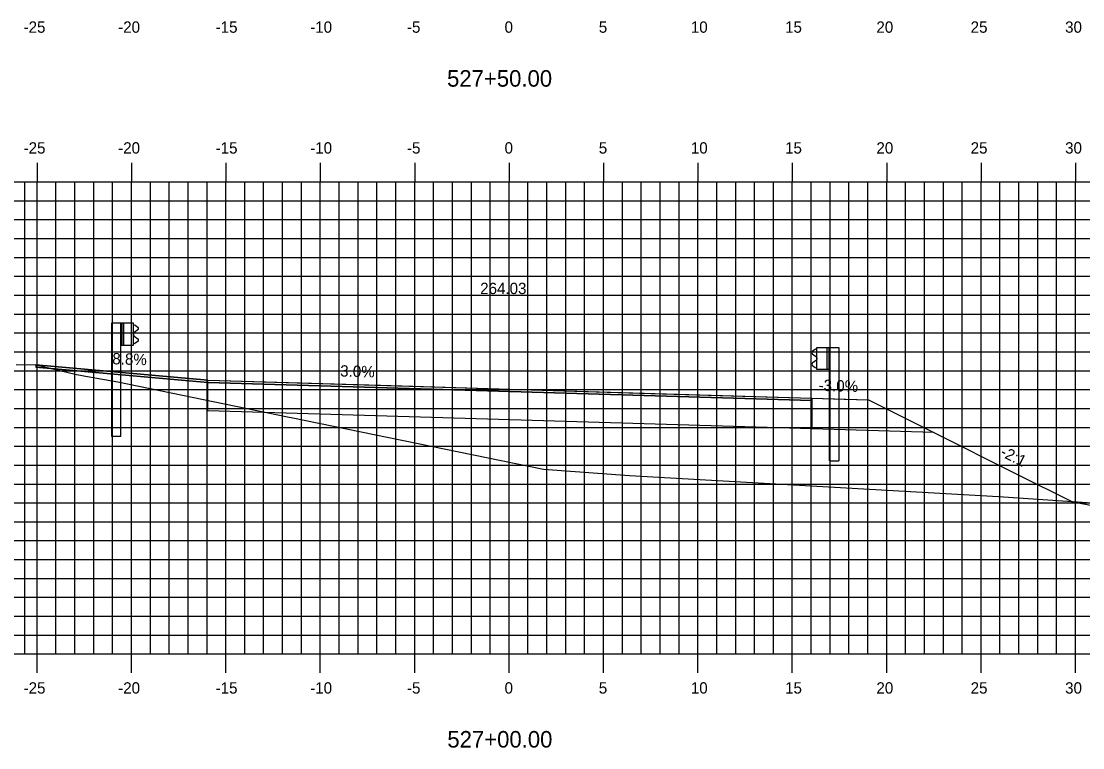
# Model space of a CAD drawing. Extents: x 1170543 to 1177585, y 609599 to 610623.
# Drawn here: x 1176144.5 to 1176200.8, y 610272.8 to 610311.3 of the extents above; entities that cross this region are included whole.
import ezdxf

# ---------------------------------------------------------------- set-up
doc = ezdxf.new("R2010")
doc.units = 0
for name, color, linetype in [('_Construction', 7, 'Continuous'), ('ANNOTATION', 7, 'Continuous'), ('D_Guardrail_Beam_Lt', 7, 'Continuous'), ('D_Guardrail_Beam_Rt', 7, 'Continuous'), ('D_Roadway_Centerline', 7, 'Continuous'), ('D_Roadway_Centerline_Text', 7, 'Continuous'), ('D_Roadway_Edge_Pavement', 7, 'Continuous'), ('D_Roadway_Edge_Shoulder', 7, 'Continuous'), ('D_Roadway_Edge_TW', 7, 'Continuous'), ('D_Roadway_Pavement', 7, 'Continuous'), ('D_Roadway_SubGrade', 7, 'Continuous'), ('H_V ANNOTATION', 7, 'Continuous'), ('MAJOR', 7, 'Continuous'), ('MINOR', 7, 'Continuous'), ('S_Roadway_Centerline', 7, 'Continuous')]:
    doc.layers.add(name, color=color, linetype=linetype)

msp = doc.modelspace()

# ---------------------------------------------------------------- linework, layer by layer
at = {"layer": '_Construction'}
for p, q in [((1176144.745, 610277.801), (1176144.745, 610302.801)), ((1176154.41, 610292.182), (1176145.315, 610292.982)), ((1176154.421, 610292.307), (1176145.326, 610293.106))]:
    msp.add_line(p, q, dxfattribs=at)
at = {"layer": 'D_Guardrail_Beam_Lt'}
for p, q in [((1176149.331, 610295.314), (1176149.331, 610289.314)), ((1176149.802, 610295.314), (1176149.331, 610295.314)), ((1176150.49, 610295.314), (1176149.802, 610295.314)), ((1176149.802, 610295.314), (1176149.802, 610294.147)), ((1176149.865, 610295.314), (1176149.865, 610294.147)), ((1176149.969, 610295.314), (1176149.969, 610294.147)), ((1176150.49, 610294.147), (1176150.49, 610295.314)), ((1176150.49, 610295.23), (1176150.564, 610295.216)), ((1176150.723, 610294.966), (1176150.528, 610294.83)), ((1176150.58, 610295.209), (1176150.723, 610295.109)), ((1176150.494, 610294.766), (1176150.494, 610294.695)), ((1176150.528, 610294.631), (1176150.723, 610294.495)), ((1176150.723, 610294.352), (1176150.58, 610294.252)), ((1176149.802, 610294.147), (1176150.49, 610294.147)), ((1176149.823, 610289.314), (1176149.823, 610294.147)), ((1176150.564, 610294.245), (1176150.49, 610294.23)), ((1176149.823, 610289.314), (1176149.331, 610289.314))]:
    msp.add_line(p, q, dxfattribs=at)
for centre, major_axis, start_param, end_param in [((1176150.556, 610295.175), (0.0417, 0), 0.959931, 1.376053), ((1176150.673, 610295.038), (0.0877, 0), 5.323254, 7.243116), ((1176150.573, 610294.766), (-0.0789, 0), 5.323254, 6.283185), ((1176150.573, 610294.695), (-0.0789, 0), 6.283185, 7.243116), ((1176150.673, 610294.423), (0.0877, 0), 5.323254, 7.243116), ((1176150.556, 610294.286), (0.0417, 0), 4.907132, 5.323254)]:
    msp.add_ellipse(centre, major_axis=major_axis, ratio=0.995501, start_param=start_param, end_param=end_param, dxfattribs=at)
at = {"layer": 'D_Guardrail_Beam_Rt'}
for p, q in [((1176186.601, 610293.928), (1176186.458, 610293.828)), ((1176186.691, 610293.949), (1176186.617, 610293.934)), ((1176186.691, 610294.032), (1176187.379, 610294.032)), ((1176186.691, 610292.866), (1176186.691, 610294.032)), ((1176187.212, 610294.032), (1176187.212, 610292.866)), ((1176187.316, 610294.032), (1176187.316, 610292.866)), ((1176187.379, 610294.032), (1176187.85, 610294.032)), ((1176187.379, 610294.032), (1176187.379, 610292.866)), ((1176187.85, 610294.032), (1176187.85, 610288.032)), ((1176186.458, 610293.685), (1176186.653, 610293.548)), ((1176186.653, 610293.349), (1176186.458, 610293.213)), ((1176186.687, 610293.484), (1176186.687, 610293.414)), ((1176186.458, 610293.07), (1176186.601, 610292.97)), ((1176186.617, 610292.963), (1176186.691, 610292.949)), ((1176187.379, 610292.866), (1176186.691, 610292.866)), ((1176187.358, 610288.032), (1176187.358, 610292.866)), ((1176187.358, 610288.032), (1176187.85, 610288.032))]:
    msp.add_line(p, q, dxfattribs=at)
for centre, major_axis, start_param, end_param in [((1176186.508, 610293.756), (-0.0877, 0), 5.323254, 7.243116), ((1176186.625, 610293.894), (-0.0417, 0), 4.907132, 5.323254), ((1176186.508, 610293.142), (-0.0877, 0), 5.323254, 7.243116), ((1176186.608, 610293.484), (0.0789, 0), 0, 0.959931), ((1176186.608, 610293.414), (0.0789, 0), 5.323254, 6.283185), ((1176186.625, 610293.004), (-0.0417, 0), 0.959931, 1.376053)]:
    msp.add_ellipse(centre, major_axis=major_axis, ratio=0.995501, start_param=start_param, end_param=end_param, dxfattribs=at)
at = {"layer": 'D_Roadway_Centerline'}
msp.add_lwpolyline([(1176145.326, 610293.106), (1176145.326, 610293.106), (1176145.326, 610293.106), (1176154.421, 610292.307), (1176154.421, 610292.307), (1176154.421, 610292.307), (1176163.579, 610292.033), (1176170.421, 610291.827), (1176177.292, 610291.619), (1176186.42, 610291.347), (1176188.135, 610291.295), (1176189.42, 610291.257), (1176190.903, 610290.515), (1176192.878, 610289.528), (1176197.239, 610287.348), (1176200.181, 610285.876)], dxfattribs=at)
at = {"layer": 'D_Roadway_Edge_Pavement'}
msp.add_lwpolyline([(1176200.17, 610285.882), (1176205.78, 610284.801), (1176207.048, 610284.379), (1176208.783, 610283.801), (1176210.06, 610283.376), (1176211.786, 610282.801), (1176218.086, 610282.801), (1176240.385, 610282.801)], dxfattribs=at)
at = {"layer": 'D_Roadway_Edge_Shoulder'}
for points in [[(1176154.421, 610292.307), (1176145.326, 610293.106), (1176145.326, 610292.981), (1176154.421, 610292.182)], [(1176186.42, 610291.347), (1176186.42, 610291.222)]]:
    msp.add_lwpolyline(points, dxfattribs=at)
at = {"layer": 'D_Roadway_Edge_TW'}
msp.add_lwpolyline([(1176154.421, 610292.182), (1176154.421, 610292.307), (1176170.421, 610291.827), (1176186.42, 610291.347), (1176186.42, 610291.222), (1176170.421, 610291.702)], close=True, dxfattribs=at)
at = {"layer": 'D_Roadway_Pavement'}
msp.add_lwpolyline([(1176154.421, 610292.182), (1176154.421, 610292.182), (1176170.421, 610291.702), (1176186.42, 610291.222), (1176186.42, 610291.222), (1176170.421, 610291.702)], close=True, dxfattribs=at)
for points in [[(1176154.421, 610292.182), (1176154.421, 610292.182)], [(1176154.421, 610292.182), (1176154.421, 610292.182)], [(1176186.42, 610291.222), (1176186.42, 610291.222)], [(1176186.42, 610291.222), (1176186.42, 610291.222)]]:
    msp.add_lwpolyline(points, dxfattribs=at)
at = {"layer": 'D_Roadway_SubGrade'}
for points in [[(1176154.421, 610290.682), (1176154.421, 610292.182), (1176170.421, 610291.702), (1176186.42, 610291.222), (1176186.42, 610289.722), (1176170.421, 610290.202)], [(1176186.42, 610291.347), (1176189.42, 610291.257), (1176192.878, 610289.528), (1176186.42, 610289.722)]]:
    msp.add_lwpolyline(points, close=True, dxfattribs=at)
at = {"layer": 'MAJOR'}
for p, q in [((1176145.385, 610303.803), (1176145.385, 610302.801)), ((1176150.385, 610303.803), (1176150.385, 610302.801)), ((1176155.385, 610303.803), (1176155.385, 610302.801)), ((1176160.385, 610303.803), (1176160.385, 610302.801)), ((1176165.385, 610303.803), (1176165.385, 610302.801)), ((1176170.385, 610303.803), (1176170.385, 610302.801)), ((1176175.385, 610303.803), (1176175.385, 610302.801)), ((1176180.385, 610303.803), (1176180.385, 610302.801)), ((1176185.385, 610303.803), (1176185.385, 610302.801)), ((1176190.385, 610303.803), (1176190.385, 610302.801)), ((1176195.385, 610303.803), (1176195.385, 610302.801)), ((1176200.385, 610303.803), (1176200.385, 610302.801)), ((1176100.385, 610302.801), (1176240.385, 610302.801)), ((1176100.385, 610302.801), (1176240.385, 610302.801)), ((1176145.385, 610277.801), (1176145.385, 610302.801)), ((1176150.385, 610277.801), (1176150.385, 610302.801)), ((1176155.385, 610277.801), (1176155.385, 610302.801)), ((1176160.385, 610277.801), (1176160.385, 610302.801)), ((1176165.385, 610277.801), (1176165.385, 610302.801)), ((1176170.385, 610277.801), (1176170.385, 610302.801)), ((1176175.385, 610277.801), (1176175.385, 610302.801)), ((1176180.385, 610277.801), (1176180.385, 610302.801)), ((1176185.385, 610277.801), (1176185.385, 610302.801)), ((1176190.385, 610277.801), (1176190.385, 610302.801)), ((1176195.385, 610277.801), (1176195.385, 610302.801)), ((1176200.385, 610277.801), (1176200.385, 610302.801)), ((1176100.385, 610297.801), (1176240.385, 610297.801)), ((1176100.385, 610292.801), (1176240.385, 610292.801)), ((1176100.385, 610287.801), (1176240.385, 610287.801)), ((1176100.385, 610282.801), (1176240.385, 610282.801)), ((1176100.385, 610277.801), (1176240.385, 610277.801)), ((1176100.385, 610277.801), (1176240.385, 610277.801)), ((1176145.385, 610276.799), (1176145.385, 610277.801)), ((1176150.385, 610276.799), (1176150.385, 610277.801)), ((1176155.385, 610276.799), (1176155.385, 610277.801)), ((1176160.385, 610276.799), (1176160.385, 610277.801)), ((1176165.385, 610276.799), (1176165.385, 610277.801)), ((1176170.385, 610276.799), (1176170.385, 610277.801)), ((1176175.385, 610276.799), (1176175.385, 610277.801)), ((1176180.385, 610276.799), (1176180.385, 610277.801)), ((1176185.385, 610276.799), (1176185.385, 610277.801)), ((1176190.385, 610276.799), (1176190.385, 610277.801)), ((1176195.385, 610276.799), (1176195.385, 610277.801)), ((1176200.385, 610276.799), (1176200.385, 610277.801))]:
    msp.add_line(p, q, dxfattribs=at)
at = {"layer": 'MINOR'}
for p, q in [((1176146.385, 610277.801), (1176146.385, 610302.801)), ((1176147.385, 610277.801), (1176147.385, 610302.801)), ((1176148.385, 610277.801), (1176148.385, 610302.801)), ((1176149.385, 610277.801), (1176149.385, 610302.801)), ((1176151.385, 610277.801), (1176151.385, 610302.801)), ((1176152.385, 610277.801), (1176152.385, 610302.801)), ((1176153.385, 610277.801), (1176153.385, 610302.801)), ((1176154.385, 610277.801), (1176154.385, 610302.801)), ((1176156.385, 610277.801), (1176156.385, 610302.801)), ((1176157.385, 610277.801), (1176157.385, 610302.801)), ((1176158.385, 610277.801), (1176158.385, 610302.801)), ((1176159.385, 610277.801), (1176159.385, 610302.801)), ((1176161.385, 610277.801), (1176161.385, 610302.801)), ((1176162.385, 610277.801), (1176162.385, 610302.801)), ((1176163.385, 610277.801), (1176163.385, 610302.801)), ((1176164.385, 610277.801), (1176164.385, 610302.801)), ((1176166.385, 610277.801), (1176166.385, 610302.801)), ((1176167.385, 610277.801), (1176167.385, 610302.801)), ((1176168.385, 610277.801), (1176168.385, 610302.801)), ((1176169.385, 610277.801), (1176169.385, 610302.801)), ((1176171.385, 610277.801), (1176171.385, 610302.801)), ((1176172.385, 610277.801), (1176172.385, 610302.801)), ((1176173.385, 610277.801), (1176173.385, 610302.801)), ((1176174.385, 610277.801), (1176174.385, 610302.801)), ((1176176.385, 610277.801), (1176176.385, 610302.801)), ((1176177.385, 610277.801), (1176177.385, 610302.801)), ((1176178.385, 610277.801), (1176178.385, 610302.801)), ((1176179.385, 610277.801), (1176179.385, 610302.801)), ((1176181.385, 610277.801), (1176181.385, 610302.801)), ((1176182.385, 610277.801), (1176182.385, 610302.801)), ((1176183.385, 610277.801), (1176183.385, 610302.801)), ((1176184.385, 610277.801), (1176184.385, 610302.801)), ((1176186.385, 610277.801), (1176186.385, 610302.801)), ((1176187.385, 610277.801), (1176187.385, 610302.801)), ((1176188.385, 610277.801), (1176188.385, 610302.801)), ((1176189.385, 610277.801), (1176189.385, 610302.801)), ((1176191.385, 610277.801), (1176191.385, 610302.801)), ((1176192.385, 610277.801), (1176192.385, 610302.801)), ((1176193.385, 610277.801), (1176193.385, 610302.801)), ((1176194.385, 610277.801), (1176194.385, 610302.801)), ((1176196.385, 610277.801), (1176196.385, 610302.801)), ((1176197.385, 610277.801), (1176197.385, 610302.801)), ((1176198.385, 610277.801), (1176198.385, 610302.801)), ((1176199.385, 610277.801), (1176199.385, 610302.801)), ((1176100.385, 610301.801), (1176240.385, 610301.801)), ((1176100.385, 610300.801), (1176240.385, 610300.801)), ((1176100.385, 610299.801), (1176240.385, 610299.801)), ((1176100.385, 610298.801), (1176240.385, 610298.801)), ((1176100.385, 610296.801), (1176240.385, 610296.801)), ((1176100.385, 610295.801), (1176240.385, 610295.801)), ((1176100.385, 610294.801), (1176240.385, 610294.801)), ((1176100.385, 610293.801), (1176240.385, 610293.801)), ((1176100.385, 610291.801), (1176240.385, 610291.801)), ((1176100.385, 610290.801), (1176240.385, 610290.801)), ((1176100.385, 610289.801), (1176240.385, 610289.801)), ((1176100.385, 610288.801), (1176240.385, 610288.801)), ((1176100.385, 610286.801), (1176240.385, 610286.801)), ((1176100.385, 610285.801), (1176240.385, 610285.801)), ((1176100.385, 610284.801), (1176240.385, 610284.801)), ((1176100.385, 610283.801), (1176240.385, 610283.801)), ((1176100.385, 610281.801), (1176240.385, 610281.801)), ((1176100.385, 610280.801), (1176240.385, 610280.801)), ((1176100.385, 610279.801), (1176240.385, 610279.801)), ((1176100.385, 610278.801), (1176240.385, 610278.801))]:
    msp.add_line(p, q, dxfattribs=at)
at = {"layer": 'S_Roadway_Centerline'}
msp.add_lwpolyline([(1176144.276, 610293.136), (1176145.326, 610293.106), (1176145.77, 610293.001), (1176146.96, 610292.728), (1176147.47, 610292.607), (1176147.679, 610292.569), (1176147.955, 610292.514), (1176148.161, 610292.477), (1176148.556, 610292.404), (1176149.659, 610292.216), (1176158.739, 610290.337), (1176158.842, 610290.317), (1176172.21, 610287.584), (1176176.758, 610287.257), (1176196.297, 610286.14), (1176207.535, 610285.377)], dxfattribs=at)

# ---------------------------------------------------------------- texts
at = {"layer": 'ANNOTATION'}
for s, rotation, p in [('8.8%', 358.2816, (1176149.361, 610293.143)), ('3.0%', 358.2816, (1176161.429, 610292.497)), ('-3.0%', 358.2816, (1176186.768, 610291.737)), ('-2:1', 333.435, (1176196.353, 610288.308))]:
    msp.add_text(s, height=0.6, rotation=rotation, dxfattribs=at).set_placement(p)
at = {"layer": 'D_Roadway_Centerline'}
for s, p in [('C', (1176170.415, 610291.827)), ('L', (1176170.421, 610291.819))]:
    msp.add_text(s, height=0.0146, dxfattribs=at).set_placement(p)
at = {"layer": 'D_Roadway_Centerline_Text'}
msp.add_text('264.03', height=0.6, dxfattribs=at).set_placement((1176168.852, 610296.86))
msp.add_text('264.03', height=0.6, dxfattribs=at).set_placement((1176168.852, 610296.86))
at = {"layer": 'H_V ANNOTATION'}
for s, height, p in [('-25', 0.6, (1176144.67, 610310.701)), ('-20', 0.6, (1176149.678, 610310.701)), ('-15', 0.6, (1176154.842, 610310.701)), ('-10', 0.6, (1176159.85, 610310.701)), ('-5', 0.6, (1176164.975, 610310.701)), ('0', 0.6, (1176170.144, 610310.701)), ('5', 0.6, (1176175.136, 610310.701)), ('10', 0.6, (1176180.01, 610310.701)), ('15', 0.6, (1176185.002, 610310.701)), ('20', 0.6, (1176189.839, 610310.701)), ('25', 0.6, (1176194.831, 610310.701)), ('30', 0.6, (1176199.834, 610310.701)), ('527+50.00', 0.875, (1176167.099, 610307.844)), ('-25', 0.6, (1176144.67, 610304.301)), ('-20', 0.6, (1176149.678, 610304.301)), ('-15', 0.6, (1176154.842, 610304.301)), ('-10', 0.6, (1176159.85, 610304.301)), ('-5', 0.6, (1176164.975, 610304.301)), ('0', 0.6, (1176170.144, 610304.301)), ('5', 0.6, (1176175.136, 610304.301)), ('10', 0.6, (1176180.01, 610304.301)), ('15', 0.6, (1176185.002, 610304.301)), ('20', 0.6, (1176189.839, 610304.301)), ('25', 0.6, (1176194.831, 610304.301)), ('30', 0.6, (1176199.834, 610304.301)), ('-25', 0.6, (1176144.67, 610275.701)), ('-20', 0.6, (1176149.678, 610275.701)), ('-15', 0.6, (1176154.842, 610275.701)), ('-10', 0.6, (1176159.85, 610275.701)), ('-5', 0.6, (1176164.975, 610275.701)), ('0', 0.6, (1176170.144, 610275.701)), ('5', 0.6, (1176175.136, 610275.701)), ('10', 0.6, (1176180.01, 610275.701)), ('15', 0.6, (1176185.002, 610275.701)), ('20', 0.6, (1176189.839, 610275.701)), ('25', 0.6, (1176194.831, 610275.701)), ('30', 0.6, (1176199.834, 610275.701)), ('527+00.00', 0.875, (1176167.115, 610272.844))]:
    msp.add_text(s, height=height, dxfattribs=at).set_placement(p)

doc.saveas('drawing.dxf')
